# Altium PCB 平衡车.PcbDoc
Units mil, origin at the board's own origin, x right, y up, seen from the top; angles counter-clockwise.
Board outline 3909.08 x 2529.71 mil, 2 copper layers (Top Layer, Bottom Layer); 10 components, 22 nets, 102 pads, 183 vias.
Unrouted connection lines stored in the file: 15.
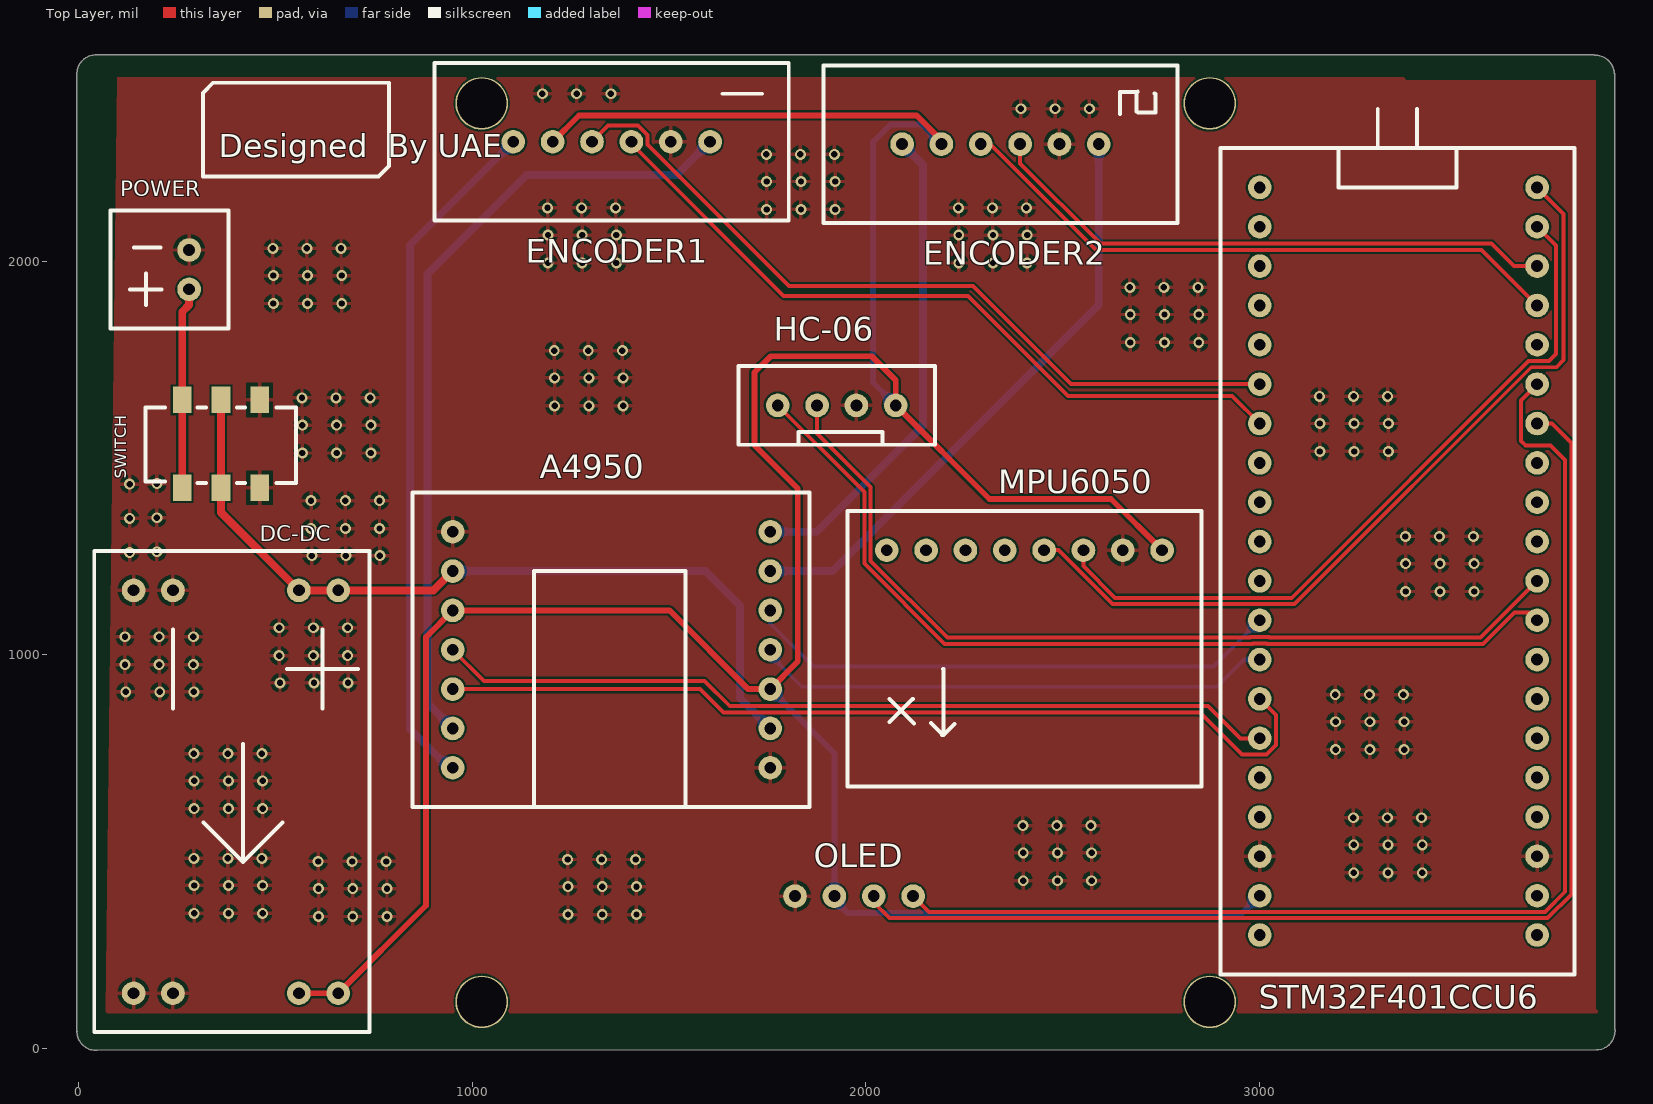
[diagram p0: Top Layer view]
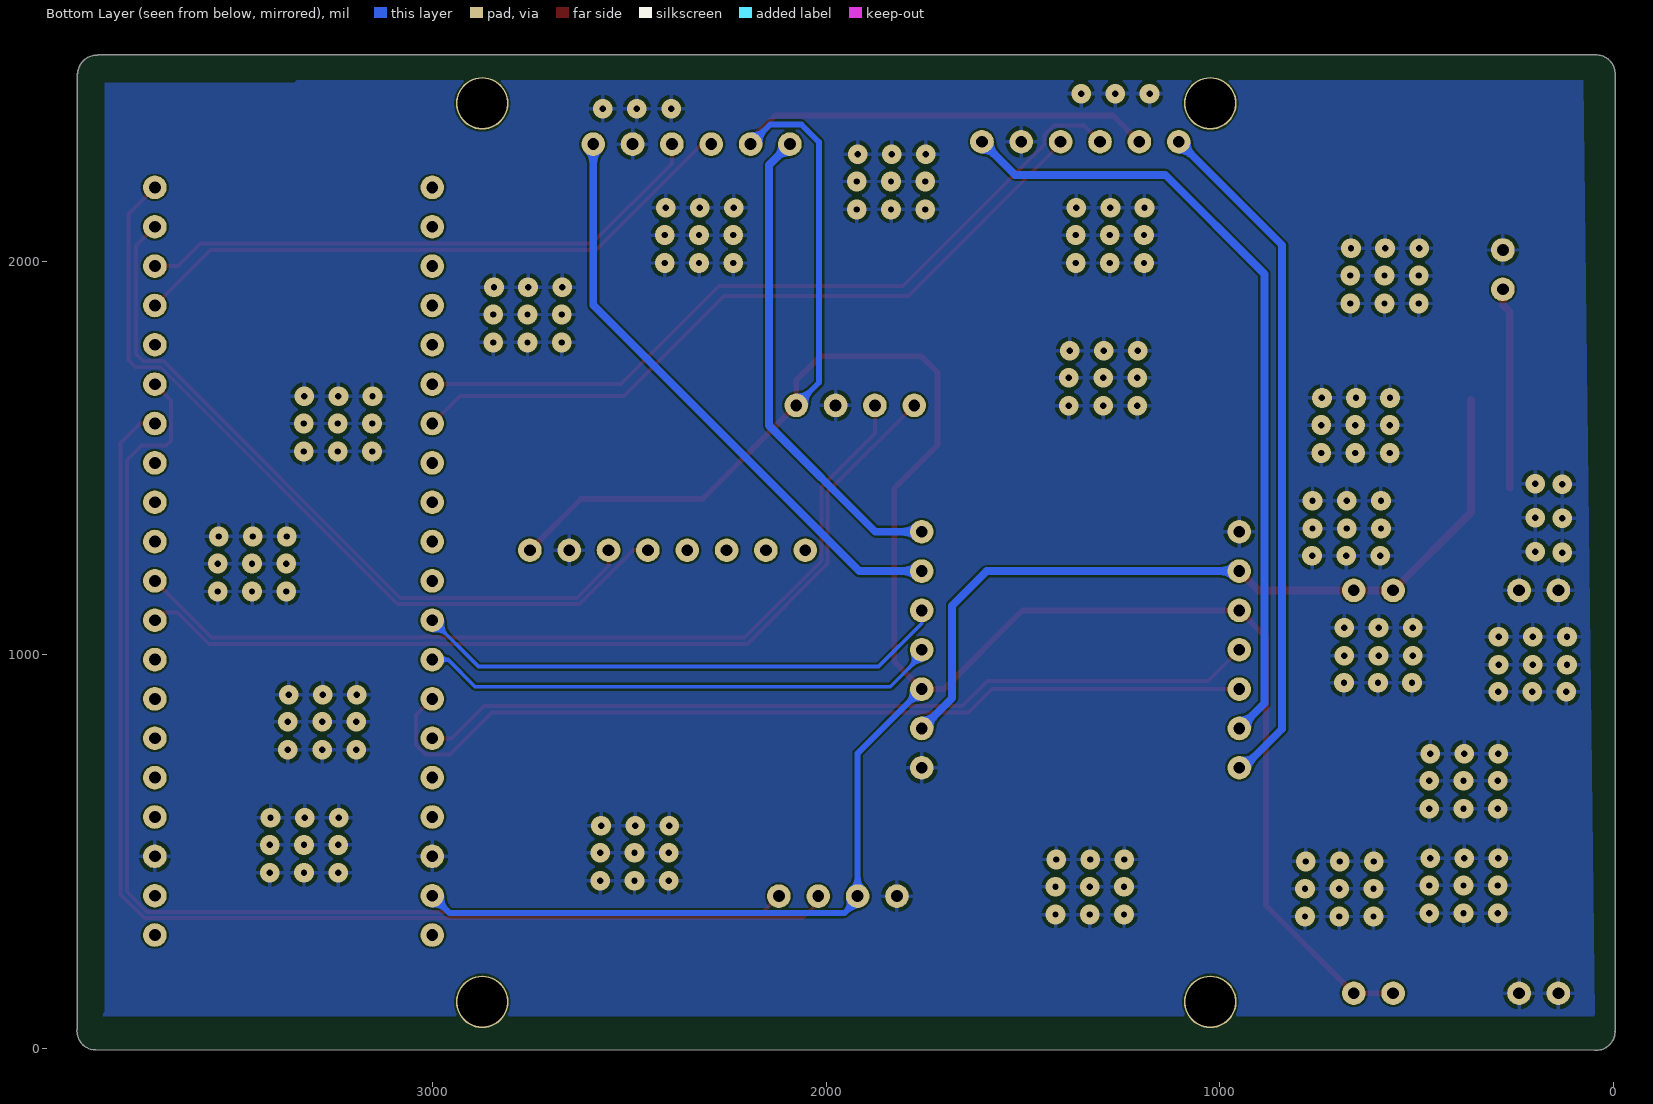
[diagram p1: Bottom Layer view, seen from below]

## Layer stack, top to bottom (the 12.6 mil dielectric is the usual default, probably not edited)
Top Solder: solder mask 0.4, Solder Resist, Dk 3.5
Top Layer: signal copper 1.4
Dielectric 1: dielectric 12.6, FR-4, Dk 4.8
Bottom Layer: signal copper 1.4
Bottom Solder: solder mask 0.4, Solder Resist, Dk 3.5

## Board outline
-5.01,40.77 cw(c0,41) -4.79,42.5 cw(c0,44) -5.01,44 -5.02,2474.57 cw(c43,2476.68) 40.68,2524.69 cw(c43,2476.68) 40.77,2524.69 40.68,2524.69 cw(c41,2519.69) 41,2524.7 3850,2524.7 cw(c3850,2519.68) 3852.49,2524.04 cw(c3854,2476) 3902,2478.4 cw(c3898.64,2474.68) 3903.65,2474.68 3903.65,47.87 cw(c3899,46) 3904.01,46.23 cw(c3856,44) 3904.06,44 cw(c3856,44) 3858.23,-4.01 cw(c3858,1) 3857,-3.91 cw(c3856,1) 3856,-4.01 46.31,-4.84 cw(c45,0) 45.23,-5.01 cw(c43,43)

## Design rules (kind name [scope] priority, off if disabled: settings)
Clearance [All] p1: gap=6 ignorepadtopadclearanceinfootprint=FALSE except(5: Arc-Poly Track-Poly SMDPad-Poly THPad-Poly Via-Poly Fill-Poly Poly-Poly)
HoleSize [All] p1: absolutevalues=TRUE maxlimit=150 minlimit=1 maxpercent=80.000 minpercent=20.000
PolygonConnect [All] p1: connectstyle=Relief reliefconductorwidth=10 reliefentries=4 polygonreliefangle="90 Angle" airgapwidth=10
RoutingVias [All] p1: holewidth=12 width=24 viastyle="Through Hole" minholewidth=12 minwidth=10 maxholewidth=135 maxwidth=150
SilkToSolderMaskClearance [IsPad] p1: minsilkscreentomaskgap=4.9 clearancetoexposedcopper=TRUE
SolderMaskExpansion [All] p1: expansion=4
Width Width_3 [InNet('12V-IN')] p1: maxlimit=20 minlimit=10 preferedwidth=20
Width Width_1 [(InNet('12V') OR InNet('12V IN'))] p2: maxlimit=20 minlimit=10 preferedwidth=20
Width Width_2 [InNet('5V')] p3: maxlimit=15 minlimit=10 preferedwidth=15
Width [All] p4: maxlimit=20 minlimit=10 preferedwidth=10
28 further rules are at their usual default settings.

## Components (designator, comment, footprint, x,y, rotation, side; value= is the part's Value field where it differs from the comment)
A4950 "A4950" A4950 1757,1313 r180 top
DC-DC "DC-DC" DC-DC 139,1164 r270 top
ENCODER1 "ENCODER1" ENCODER1 1604,2304 r270 top
ENCODER2 "ENCODER2" ENCODER2 2592,2298 r270 top
HC-06 "HC-06" HC-06 1776,1634 r270 top
MPU6050 "MPU6050" MPU6050 2753,1266 r270 top
OLED "OLED" OLED 1820,387 r0 top
POWER "POWER" POWER 280,2029 r0 top
STM32F401CCU6 "STM32F401CCU6" STM32F401CCU6 3001,288 r0 top
SWITCH "SWITCH" SIWITCH 262.57,1424.69 r0 top

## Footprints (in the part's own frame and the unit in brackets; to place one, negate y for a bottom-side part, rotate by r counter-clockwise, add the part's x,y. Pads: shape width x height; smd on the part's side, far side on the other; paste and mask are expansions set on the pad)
A4950 [mil]
  round 60 hole 30: 1(0,600) 2(0,500) 3(0,400) 4(0,300) 5(0,200) 6(0,100) 7(0,0) 8(807,600) 9(807,500) 10(807,400) 11(807,300) 12(807,200) 13(807,100) 14(807,0)
  silkscreen extent -100,-100 909,700
DC-DC [mil]
  round 60 hole 30: 1(0,0) 2(0,100) 3(0,420) 4(0,520) 5(1024,0) 6(1024,100) 7(1024,420) 8(1024,520)
  silkscreen extent -100,-100 1123,600
ENCODER1 [mil]
  round 60 hole 30: 1(0,0) 2(0,-100) 3(0,-200) 4(0,-300) 5(0,-400) 6(0,-500)
  silkscreen extent -200,-700 200,200
ENCODER2 [mil]
  round 60 hole 30: 1(0,0) 2(0,-100) 3(0,-200) 4(0,-300) 5(0,-400) 6(0,-500)
  silkscreen extent -200,-700 200,200
HC-06 [mil]
  round 60 hole 30: 1(0,0) 2(0,100) 3(0,200) 4(0,300)
  silkscreen extent -100,-100 100,400
MPU6050 [mil]
  round 60 hole 30: 1(0,0) 2(0,-100) 3(0,-200) 4(0,-300) 5(0,-400) 6(0,-500) 7(0,-600) 8(0,-700)
  silkscreen extent -100,-800 600,100
OLED [mil]
  round 60 hole 30: 1(0,0) 2(100,0) 3(200,0) 4(300,0)
POWER [mil]
  round 60 hole 30: 1(0,0) 2(0,-100)
  silkscreen extent -200,-200 100,100
SIWITCH [mm]
  rect 1.2x1.7 smd: 1(0,5.672) 2(2.5,5.672) 3(5,5.672) 4(0,0) 5(2.5,0) 6(5,0)
  silkscreen extent -2.36,0.3 7.34,5.18
STM32F401CCU6 [mil]
  round 60 hole 30: 1(0,1900) 2(0,1800) 3(0,1700) 4(0,1600) 5(0,1500) 6(0,1400) 7(0,1300) 8(0,1200) 9(0,1100) 10(0,1000) 11(0,900) 12(0,800) 13(0,700) 14(0,600) 15(0,500) 16(0,400) 17(0,300) 18(0,200) 19(0,100) 20(0,0) 21(705,1900) 22(705,1800) 23(705,1700) 24(705,1600) 25(705,1500) 26(705,1400) 27(705,1300) 28(705,1200) 29(705,1100) 30(705,1000) 31(705,900) 32(705,800) 33(705,700) 34(705,600) 35(705,500) 36(705,400) 37(705,300) 38(705,200) 39(705,100) 40(705,0)
  silkscreen extent -100,-100 800,2100

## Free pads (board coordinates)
  round 133.86 hole 125.98: 2(1023.62,118.11) 2(1023.62,2401.57) 2(2874.02,118.11) 2(2874.02,2401.57)

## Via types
v1: diameter 27.8/50 (per signal layer), hole 16.18, Top Layer to Bottom Layer, 183 vias

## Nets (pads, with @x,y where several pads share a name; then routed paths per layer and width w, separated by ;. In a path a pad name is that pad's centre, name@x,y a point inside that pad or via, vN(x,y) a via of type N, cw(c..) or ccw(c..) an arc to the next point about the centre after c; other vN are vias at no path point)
5V: A4950.3 A4950.12 DC-DC.7 DC-DC.8 ENCODER1.5 ENCODER2.5 HC-06.4 MPU6050.1 OLED.2 STM32F401CCU6.19 | length 7932.7
  Top Layer w15: DC-DC.7 DC-DC.8 882,363 882,1045 A4950.12 1501,1113 1701,913 A4950.3 1827,983 1827,1423 1717,1533 1717,1718 1758,1759 2015,1759 2076,1698 HC-06.4 2314,1396 2623,1396 MPU6050.1 ; ENCODER1.5 1271,2371 2129,2371 2192,2308 ENCODER2.5
  Bottom Layer w15: A4950.3 1920,750 OLED.2 1920,377 1953.5,343.5 2956.5,343.5 STM32F401CCU6.19 ; HC-06.4 2018,1692 2018,2303 2063,2348 2142,2348 ENCODER2.5
12V: A4950.2 A4950.13 DC-DC.3 DC-DC.4 SWITCH.2 SWITCH.5 | length 2087.7
  Top Layer w20: SWITCH.2 SWITCH.5 361,1362 DC-DC.3 DC-DC.4 901,1164 A4950.13
  Bottom Layer w20: A4950.13 1592,1213 1680,1125 1680,890 A4950.2
12V-IN: POWER.2 SWITCH.1 SWITCH.4 | length 511.5
  Top Layer w20: SWITCH.4 SWITCH.1 262.57,1871.82 280,1889.25 POWER.2
AIN1: A4950.5 STM32F401CCU6.12 | length 1371.4
  Bottom Layer w10: A4950.5 1757,1080 1867,970 2883,970 STM32F401CCU6.12
AIN2: A4950.4 STM32F401CCU6.13 | length 1325.5
  Bottom Layer w10: A4950.4 1750,1006 1837,919 2892,919 2961,988 STM32F401CCU6.13
AOUT1: A4950.9 ENCODER1.1 | length 2038.7
  Bottom Layer w20: A4950.9 886,877 886,1968 1138,2220 1520,2220 ENCODER1.1
AOUT2: A4950.8 ENCODER1.6 | length 1750.9
  Bottom Layer w20: A4950.8 940,713 841,812 841,2041 ENCODER1.6
BIN1: A4950.10 STM32F401CCU6.14 | length 2304.7
  Top Layer w10: A4950.10 1579,913 1638,854 2849.31,854 2956.31,747 3018,747 3042,771 3042,847 STM32F401CCU6.14
BIN2: A4950.11 STM32F401CCU6.15 | length 2144.2
  Top Layer w10: A4950.11 1029,934 1590,934 1654,870 2870,870 2952,788 STM32F401CCU6.15
BOUT1: A4950.6 ENCODER2.1 | length 1524
  Bottom Layer w20: A4950.6 1916,1213 2592,1889 ENCODER2.1
BOUT2: A4950.7 ENCODER2.6 | length 1236.8
  Bottom Layer w20: A4950.7 1875,1313 2145,1583 2145,2245 ENCODER2.6
EN1A: ENCODER1.4 STM32F401CCU6.6 | length 2000.2
  Top Layer w10: ENCODER1.4 1345,2345 1420.98,2345 1445,2320.98 1445,2297 1805,1937 2272,1937 2521,1688 STM32F401CCU6.6
EN1B: ENCODER1.3 STM32F401CCU6.7 | length 1895
  Top Layer w10: ENCODER1.3@1401.5,2301.5 1791,1912 2260,1912 2514,1658 2931,1658 STM32F401CCU6.7
EN2A: ENCODER2.4 STM32F401CCU6.24 | length 1583.8
  Top Layer w10: ENCODER2.4 2316,2298 2585,2029 3565,2029 STM32F401CCU6.24
EN2B: ENCODER2.3 STM32F401CCU6.23 | length 1471.1
  Top Layer w10: ENCODER2.3 2392,2249 2596,2045 3590,2045 3647,1988 STM32F401CCU6.23
GND: A4950.1 A4950.14 DC-DC.1 DC-DC.2 DC-DC.5 DC-DC.6 ENCODER1.2 ENCODER2.2 HC-06.3 MPU6050.2 OLED.1 POWER.1 STM32F401CCU6.18 STM32F401CCU6.38 SWITCH.3 SWITCH.6
  other v1: 609,335 696,335 783,335 1243,340 1330,340 1417,340 293,343 380,343 467,343 609,406 696,406 783,406 1243,411 1330,411 1417,411 293,414 380,414 467,414 2400,426 2487,426 2574,426 3240,446 3327,446 3414,446 608,475 694.5,475 781,475 1242,480 1328.5,480 1415,480 292,483 378.5,483 465,483 2400,497 2487,497 2574,497 3240,517 3327,517 3414,517 2399,566 2485.5,566 2572,566 3239,586 3325.5,586 3412,586 293,609 380,609 467,609 293,680 380,680 467,680 292,749 378.5,749 465,749 3194,759 3281,759 3368,759 3194,830 3281,830 3368,830 3193,899 3279.5,899 3366,899 119,906 205.5,906 292,906 511,929 597.5,929 684,929 117,975 204,975 291,975 509,998 596,998 683,998 117,1046 204,1046 291,1046 509,1069 596,1069 683,1069 3372,1161 3459,1161 3546,1161 3372,1232 3459,1232 3546,1232 592,1252 678.5,1252 765,1252 129,1260 198,1262 3371,1301 3457.5,1301 3544,1301 590,1321 677,1321 764,1321 129,1347 198,1348.5 590,1392 677,1392 764,1392 129,1434 198,1435 568,1513 655,1513 742,1513 3154,1517 3241,1517 3328,1517 568,1584 655,1584 742,1584 3154,1588 3241,1588 3328,1588 1209,1633 1296,1633 1383,1633 567,1653 653.5,1653 740,1653 3153,1657 3239.5,1657 3326,1657 1209,1704 1296,1704 1383,1704 1208,1773 1294.5,1773 1381,1773 2672,1794 2759,1794 2846,1794 2672,1865 2759,1865 2846,1865 494,1893 581,1893 668,1893 2671,1934 2757.5,1934 2844,1934 494,1964 581,1964 668,1964 1192,1996 1279,1996 1366,1996 2236,1996 2323,1996 2410,1996 493,2033 579.5,2033 666,2033 1192,2067 1279,2067 1366,2067 2236,2067 2323,2067 2410,2067 1748,2132 1835,2132 1922,2132 1191,2136 1277.5,2136 1364,2136 2235,2136 2321.5,2136 2408,2136 1748,2203 1835,2203 1922,2203 1747,2272 1833.5,2272 1920,2272 2394,2388 2481,2388 2568,2388 1178,2426 1265,2426 1352,2426
HC-05_RX: HC-06.1 STM32F401CCU6.32 | length 2329.6
  Top Layer w10: HC-06.1 1996,1414 1996,1232.39 2200.39,1028 2983.02,1028 2984.02,1029 3017.98,1029 3018.98,1028 3568.63,1028 3648.63,1108 3686,1108 STM32F401CCU6.32
HC-05_TX: HC-06.2 STM32F401CCU6.31 | length 2286.6
  Top Layer w10: HC-06.2 1876,1563 2012,1427 2012,1239.02 2207.02,1044 2976.39,1044 2977.39,1045 3024.61,1045 3025.61,1044 3562,1044 STM32F401CCU6.31
MPU_SCL: MPU6050.3 STM32F401CCU6.22 | length 1874.5
  Top Layer w10: MPU6050.3 2553,1225.63 2633.63,1145 3082.39,1145 3684.39,1747 3736,1747 3754,1765 3754,2040 STM32F401CCU6.22
MPU_SDA: MPU6050.4 STM32F401CCU6.21 | length 2100.3
  Top Layer w10: MPU6050.4 2490,1266 2627,1129 3089.02,1129 3691.02,1731 3755,1731 3773,1749 3773,2121 STM32F401CCU6.21
OLED_SCL: OLED.3 STM32F401CCU6.27 | length 3085.5
  Top Layer w10: OLED.3 2020,371 2060,331 3732.63,331 3793,391.37 3793,1539 3744,1588 STM32F401CCU6.27
OLED_SDA: OLED.4 STM32F401CCU6.26 | length 3085
  Top Layer w10: OLED.4 2160,347 3726,347 3777,398 3777,1495 3740,1532 3677,1532 3665,1544 3665,1647 STM32F401CCU6.26
pads on no net: MPU6050.5 MPU6050.6 MPU6050.7 MPU6050.8 STM32F401CCU6.1 STM32F401CCU6.2 STM32F401CCU6.3 STM32F401CCU6.4 STM32F401CCU6.5 STM32F401CCU6.8 STM32F401CCU6.9 STM32F401CCU6.10 STM32F401CCU6.11 STM32F401CCU6.16 STM32F401CCU6.17 STM32F401CCU6.20 STM32F401CCU6.25 STM32F401CCU6.28 STM32F401CCU6.29 STM32F401CCU6.30 STM32F401CCU6.33 STM32F401CCU6.34 STM32F401CCU6.35 STM32F401CCU6.36 STM32F401CCU6.37 STM32F401CCU6.39 STM32F401CCU6.40

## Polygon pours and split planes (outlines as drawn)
GND on Top Layer "Top Layer-GND" (solid, remove dead copper, pour order 2): 98,2468 3367,2468 3374,2461 3855,2461 3855,100 3864,91 3862,89 68,89
GND on Bottom Layer "Bottom Layer-GND" (solid, remove dead copper, pour order 0): 76,2461 3345,2461 3352,2454 3833,2454 3833,93 3842,84 3840,82 46,82

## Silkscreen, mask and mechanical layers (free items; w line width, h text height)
Top Overlay:
  lines w10: 315,2215.7 761.7,2215.7 788,2242 788,2454 341,2454 315,2428 315,2215.7
  text "Designed  By UAE" at 355,2245.69 h100
Mechanical 1:
  lines w10: 0,41 ccw(c43,43) 45,0 ; 0,44 0,2474.68 cw(c43,2476.68) 41,2519.68 3850,2519.68 ; 45,0.17 3856,1 ; 3852,2519 cw(c3854,2476) 3897,2478 ; 3858,1 ccw(c3856,44) 3899,46 ; 3898.64,43 3898.64,2474.68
